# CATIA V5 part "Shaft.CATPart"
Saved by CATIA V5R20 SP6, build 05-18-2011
Part number: Shaft
Bounding box of the stored display mesh (mm): x -5 to 5, y 0 to 58, z -4.99 to 4.99
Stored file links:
  E:\#01 CATIA Lecture Materials\#06 DMU\#06 DMU Page01 KIN EX06\Shaft.CATPart
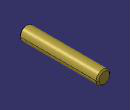
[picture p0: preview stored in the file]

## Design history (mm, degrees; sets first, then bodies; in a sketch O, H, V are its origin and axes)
Body1 (main body)
  Solid1: solid without history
